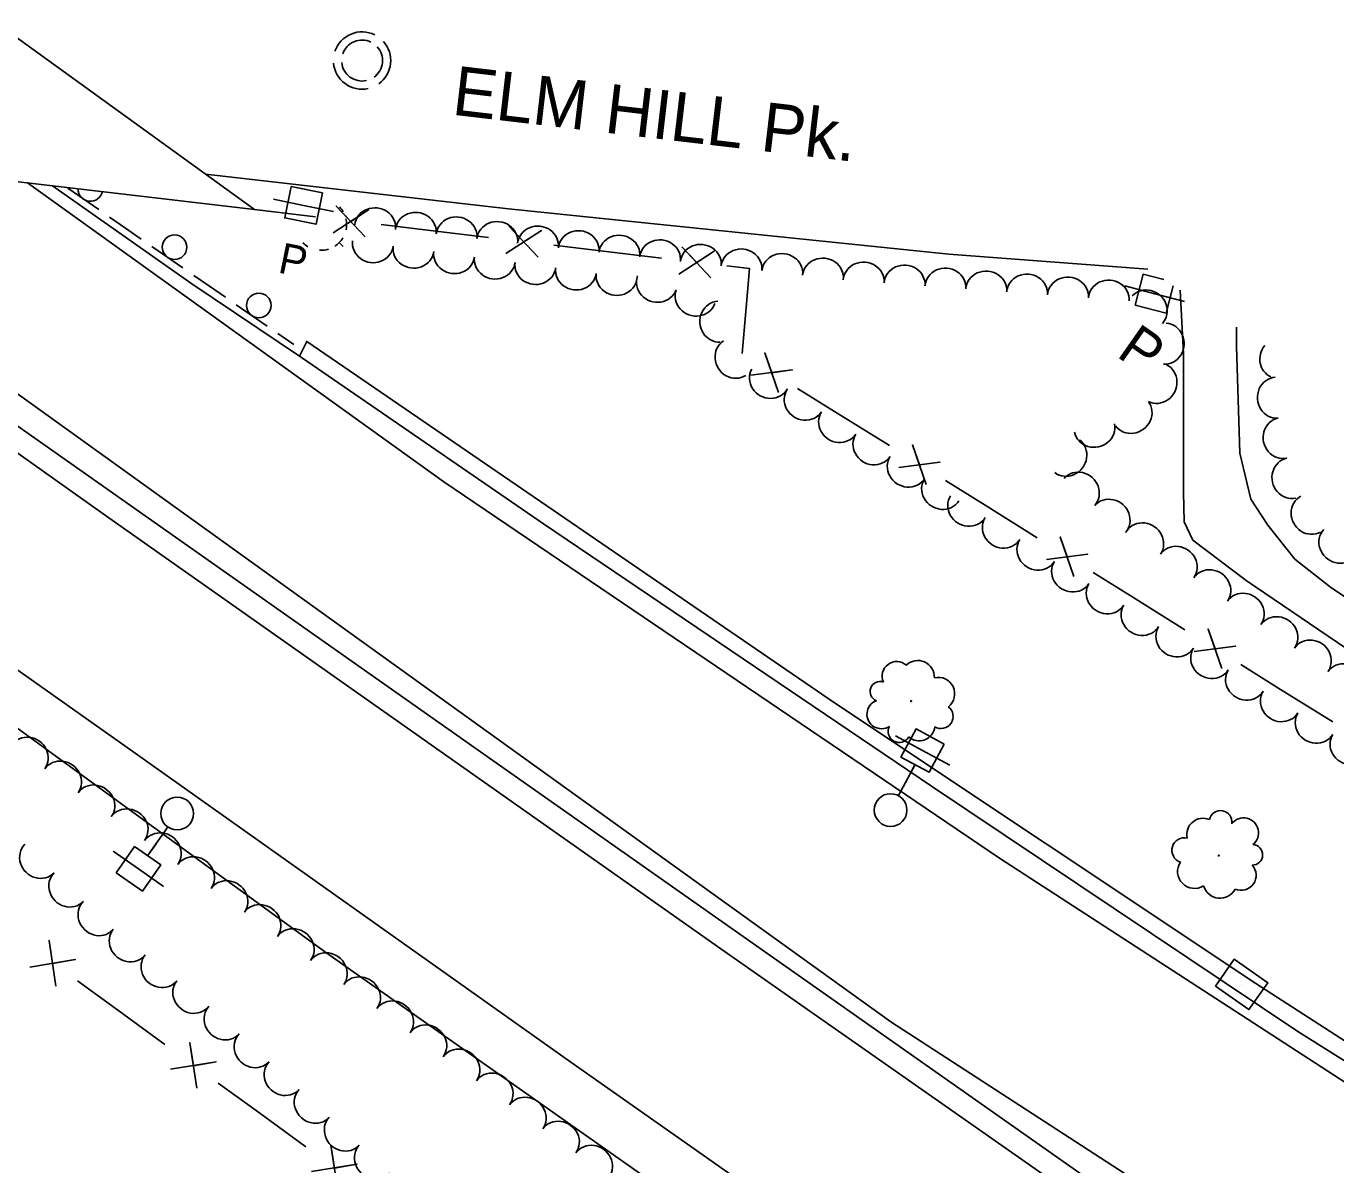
# Model space of a CAD drawing. Extents: x 1746010 to 1754829, y 655801 to 663091.
# Drawn here: x 1750620.5 to 1750940.1, y 659729.4 to 660007.5 of the extents above; entities that cross this region are included whole.
import ezdxf

# ---------------------------------------------------------------- set-up
doc = ezdxf.new("R2010")
doc.units = 0
for name, color, linetype in [('SURVEY - AERIAL SURVEY - Photo Control - Points - Elevations', 7, 'Continuous'), ('SURVEY - AERIAL SURVEY - Photo Control - Points - Locators', 7, 'Continuous'), ('SURVEY - AERIAL SURVEY - Photo Control - Points - Numbers', 7, 'Continuous'), ('SURVEY - CENTERLINE - Existing Roads - Development', 7, 'Continuous'), ('SURVEY - CENTERLINE - Existing Roads Curve Text', 7, 'Continuous'), ('SURVEY - CENTERLINE - Existing Roads Text', 7, 'Continuous'), ('SURVEY - CENTERLINE - Preliminary - Development', 7, 'Continuous'), ('SURVEY - CONTROL - Points - Numbers', 7, 'Continuous')]:
    doc.layers.add(name, color=color, linetype=linetype)

msp = doc.modelspace()

# ---------------------------------------------------------------- linework, layer by layer
at = {"layer": 'SURVEY - AERIAL SURVEY - Photo Control - Points - Elevations'}
for points in [[(1750204.41, 660084.58), (1750567.39, 660041.45), (1750676.22, 659962.69), (1750316.04, 660004.98)], [(1751901.75, 659229.66), (1751903.78, 659232.49), (1751820.15, 659271.12), (1751720.09, 659319), (1751608.79, 659375.48), (1751511.86, 659425.67), (1751414.79, 659477.82), (1751309.42, 659535.79), (1751238.02, 659576.37), (1751119.98, 659647.33), (1751011.07, 659715.27), (1750920.63, 659773.68), (1750818.05, 659842.07), (1750688.97, 659930.51), (1750687.2, 659926.86)]]:
    msp.add_lwpolyline(points, dxfattribs=at)
at = {"layer": 'SURVEY - AERIAL SURVEY - Photo Control - Points - Locators'}
for points in [[(1751850.89, 659069.97), (1751836.71, 659078.71), (1751698.09, 659167.45), (1751556.82, 659259.91), (1751409.51, 659356.6), (1751240.26, 659471.26), (1751108.21, 659560.28), (1750949.44, 659670.61), (1750790.01, 659782.16), (1750639.25, 659888.39), (1750537.27, 659960.87), (1750507.28, 659982.53)], [(1751692.52, 659270.52), (1751605.65, 659313.28), (1751476.09, 659381.66), (1751353.72, 659447.67), (1751225.98, 659520.03), (1751088.26, 659602.44), (1750950.33, 659687.25), (1750831.52, 659764.33), (1750532.19, 659979.6)], [(1750664.23, 659971.37), (1750738.22, 659962.83), (1750845.67, 659951.8), (1750894.23, 659948.17)], [(1751980.95, 659190.5), (1751865.03, 659241.97), (1751755.82, 659292.86), (1751627.46, 659356.04), (1751498.69, 659424), (1751376.94, 659489.68), (1751250.14, 659561.52), (1751113.15, 659643.48), (1750975.97, 659727.83), (1750858.05, 659804.33), (1750722.4, 659896.24), (1750620.83, 659969.19)], [(1750687.69, 659926.53), (1750660.89, 659944.53), (1750626.94, 659968.47)], [(1751811.46, 659040.6), (1751803.54, 659045.66), (1751651.7, 659139.14), (1751560.97, 659192.86), (1751430.95, 659277.83), (1751226.31, 659416.5), (1751044.68, 659538.71), (1750870.37, 659656.91), (1750693.9, 659781.14), (1750567.77, 659872.76), (1750445.81, 659959.59)], [(1750464.75, 659959.09), (1750533.91, 659909.95), (1750645.13, 659831.38), (1750753.4, 659754.5), (1750870.59, 659672.13), (1750959.5, 659609.93), (1751081.2, 659527.03), (1751199.52, 659445.74), (1751320.31, 659364.23), (1751443.12, 659281.31), (1751559.93, 659204.83), (1751660.4, 659140.92), (1751744.29, 659087.1), (1751814.04, 659042.53)], [(1750902.16, 659942.97), (1750902.94, 659927.48), (1750902.95, 659893.71), (1750903.13, 659886.46), (1750905.25, 659881.98), (1750918.24, 659872.14), (1750993.75, 659820.81), (1750998.91, 659830.33), (1750938.84, 659870.48), (1750930.13, 659877.33), (1750923.58, 659885.66), (1750919.37, 659891.98), (1750916.72, 659903.21), (1750915.86, 659929.32), (1750915.87, 659933.99)], [(1751981.66, 659195.26), (1751889.68, 659234.85), (1751784.21, 659284.64), (1751694.2, 659328.1), (1751603.81, 659373.71), (1751512.94, 659420.78), (1751440.06, 659459.77), (1751340.52, 659515.91), (1751224.32, 659581.45), (1751125.19, 659640.31), (1751025.2, 659702.76), (1750930.86, 659762.02), (1750841.47, 659821.93), (1750746.73, 659885.97), (1750687.69, 659926.53)]]:
    msp.add_lwpolyline(points, dxfattribs=at)
at = {"layer": 'SURVEY - AERIAL SURVEY - Photo Control - Points - Numbers'}
for points in [[(1751210.77, 659498.28), (1751086.47, 659583.36), (1750914.66, 659701.33), (1750734.42, 659828.18), (1750551.67, 659956.79), (1750517.76, 659981.3)], [(1750638.18, 659962.67), (1750630.61, 659967.9)], [(1750644.68, 659958.17), (1750640.81, 659960.84)], [(1750648.54, 659955.5), (1750644.68, 659958.17)], [(1750658.74, 659948.44), (1750651.17, 659953.68)], [(1750665.24, 659943.95), (1750661.37, 659946.62)], [(1750669.1, 659941.27), (1750665.24, 659943.95)], [(1750679.3, 659934.22), (1750671.74, 659939.45)], [(1750685.8, 659929.72), (1750681.93, 659932.4)]]:
    msp.add_lwpolyline(points, dxfattribs=at)
for centre, start in [((1750636.14, 659967.72), 179.5986), ((1750656.7, 659953.5), 348.595), ((1750677.26, 659939.28), 348.595)]:
    msp.add_arc(centre, 3, start, 348.581, dxfattribs=at)
at = {"layer": 'SURVEY - CENTERLINE - Existing Roads - Development'}
for points in [[(1750676.22, 659962.69), (1750691.12, 659960.91)], [(1750695.38, 659956.99), (1750704.02, 659962.61), (1750699.75, 659959.8), (1750696.17, 659963.55), (1750703.22, 659956.06)], [(1750707.1, 659959.01), (1750718.43, 659957.66)], [(1750737.58, 659951.96), (1750746.22, 659957.59), (1750741.95, 659954.77), (1750738.38, 659958.52), (1750745.43, 659951.03)], [(1750718.43, 659957.66), (1750733.32, 659955.88)], [(1750749.31, 659953.98), (1750760.63, 659952.63)], [(1750760.63, 659952.63), (1750775.53, 659950.85)], [(1750779.79, 659946.94), (1750788.42, 659952.56), (1750784.16, 659949.74), (1750780.58, 659953.49), (1750787.63, 659946)], [(1750791.51, 659948.95), (1750797.07, 659948.29), (1750796.56, 659942.51)], [(1750796.56, 659942.51), (1750795.25, 659927.58)], [(1750797.38, 659922.22), (1750807.45, 659923.52), (1750802.46, 659922.84), (1750800.74, 659927.7), (1750804.08, 659918.04)], [(1750808.78, 659919), (1750818.45, 659912.97)], [(1750818.45, 659912.97), (1750831.18, 659905.04)], [(1750833.45, 659899.74), (1750843.52, 659901.04), (1750838.53, 659900.37), (1750836.81, 659905.22), (1750840.15, 659895.56)], [(1750844.85, 659896.52), (1750854.52, 659890.49)], [(1750854.52, 659890.49), (1750867.25, 659882.56)], [(1750869.52, 659877.26), (1750879.59, 659878.57), (1750874.59, 659877.89), (1750872.88, 659882.74), (1750876.22, 659873.08)], [(1750880.92, 659874.04), (1750890.59, 659868.01)], [(1750890.59, 659868.01), (1750903.32, 659860.08)], [(1750905.59, 659854.78), (1750915.66, 659856.09), (1750910.67, 659855.41), (1750908.95, 659860.27), (1750912.29, 659850.61)], [(1750916.99, 659851.57), (1750926.66, 659845.54)], [(1750926.66, 659845.54), (1750939.39, 659837.6)], [(1750621.35, 659777.74), (1750632.45, 659779.57), (1750626.94, 659778.63), (1750626.05, 659784.22), (1750627.74, 659773.1)], [(1750632.99, 659774.36), (1750642.21, 659767.66)], [(1750642.21, 659767.66), (1750654.34, 659758.84)], [(1750655.74, 659752.76), (1750666.83, 659754.59), (1750661.32, 659753.65), (1750660.44, 659759.23), (1750662.13, 659748.12)], [(1750667.37, 659749.38), (1750676.59, 659742.68)], [(1750676.59, 659742.68), (1750688.73, 659733.86)], [(1750690.12, 659727.78), (1750701.21, 659729.61), (1750695.71, 659728.66), (1750694.82, 659734.25), (1750696.51, 659723.14)]]:
    msp.add_lwpolyline(points, dxfattribs=at)
at = {"layer": 'SURVEY - CENTERLINE - Existing Roads Curve Text'}
for p, q in [((1750688.18, 659963.7), (1750680.83, 659965.2)), ((1750688.18, 659963.7), (1750695.53, 659962.19)), ((1750697.84, 659953.64), (1750696.85, 659954.63)), ((1750895.94, 659942.14), (1750888.68, 659944.03)), ((1750895.94, 659942.14), (1750903.2, 659940.24)), ((1750839.28, 659830.59), (1750832.67, 659834.15)), ((1750839.28, 659830.59), (1750845.89, 659827.04)), ((1750833.31, 659819.49), (1750837.43, 659827.16)), ((1750837.24, 659826.81), (1750835.73, 659823.99)), ((1750655.1, 659812.03), (1750650.11, 659804.9)), ((1750650.34, 659805.22), (1750652.18, 659807.85)), ((1750647.88, 659801.7), (1750641.73, 659806)), ((1750647.88, 659801.7), (1750654.02, 659797.4))]:
    msp.add_line(p, q, dxfattribs=at)
for points in [[(1750685.14, 659968.3), (1750692.79, 659966.74), (1750691.22, 659959.09), (1750683.58, 659960.66)], [(1750844.56, 659832.18), (1750840.87, 659825.31), (1750834, 659829.01), (1750837.69, 659835.88)], [(1750642.45, 659800.74), (1750646.92, 659807.13), (1750653.31, 659802.66), (1750648.84, 659796.27)]]:
    msp.add_lwpolyline(points, close=True, dxfattribs=at)
msp.add_lwpolyline([(1750900.48, 659944.08), (1750898.73, 659937.38), (1750891.18, 659939.35), (1750893.15, 659946.9), (1750898.18, 659945.58)], dxfattribs=at)
for centre in [(1750657.34, 659815.22), (1750831.47, 659816.06)]:
    msp.add_circle(centre, 4, dxfattribs=at)
for start, end in [(30.0335, 43.9229), (348.4097, 13.1798), (302.3679, 328.8832), (224.847, 239.4679), (266.7248, 287.0674)]:
    msp.add_arc((1750692.44, 659958.99), 6.25, start, end, dxfattribs=at)
at = {"layer": 'SURVEY - CENTERLINE - Existing Roads Text'}
for centre, radius in [((1750836.48, 659842.68), 0.123), ((1750911.57, 659804.96), 0.128)]:
    msp.add_circle(centre, radius, dxfattribs=at)
for centre, radius, start, end in [((1750838.13, 659848.55), 4.03, 356.9893, 134.5135), ((1750832.94, 659848.79), 3.54, 47.9365, 204.7255), ((1750828.89, 659845.03), 2.43, 70.0527, 248.7983), ((1750843.1, 659844.45), 4.01, 307.8851, 103.7236), ((1750829.23, 659839.45), 3.53, 110.0734, 303.4931), ((1750843.79, 659838.92), 2.95, 238.138, 53.1383), ((1750833.56, 659835.27), 2.69, 152.6921, 330.0112), ((1750838.44, 659836.76), 3.81, 227.9791, 354.8248), ((1750912.01, 659813.17), 2.78, 351.1185, 168.4377), ((1750907.72, 659810.13), 3.93, 66.4056, 193.2512), ((1750917.63, 659810.5), 3.65, 308.4999, 141.9195), ((1750903.18, 659806.26), 3.05, 76.5645, 251.5648), ((1750919.77, 659805.14), 2.51, 268.4792, 87.2248), ((1750905.66, 659801.07), 4.14, 146.3116, 302.1501), ((1750917.04, 659800.13), 3.65, 246.363, 43.1519), ((1750911.88, 659798.67), 4.16, 195.4158, 332.94)]:
    msp.add_arc(centre, radius, start, end, dxfattribs=at)
for centre, major_axis, start_param in [((1750705.66, 659958.41), (4.97, -0.56), 0), ((1750715.59, 659957.29), (4.97, -0.56), 0), ((1750725.53, 659956.18), (4.97, -0.56), 0), ((1750735.46, 659955.06), (4.97, -0.56), 0), ((1750745.4, 659953.94), (4.97, -0.56), 0), ((1750705.11, 659954.42), (-4.96, 0.66), 0), ((1750755.34, 659952.83), (4.97, -0.56), 0), ((1750765.27, 659951.71), (4.97, -0.56), 0), ((1750775.21, 659950.59), (4.97, -0.56), 0), ((1750715.02, 659953.09), (-4.96, 0.66), 0), ((1750724.93, 659951.76), (-4.96, 0.66), 0), ((1750785.14, 659949.47), (4.97, -0.56), 0), ((1750795.08, 659948.36), (4.97, -0.56), 0), ((1750805.02, 659947.24), (4.97, -0.56), 0), ((1750734.85, 659950.43), (-4.96, 0.66), 0), ((1750744.76, 659949.1), (-4.96, 0.66), 0), ((1750814.95, 659946.12), (4.97, -0.56), 0), ((1750824.9, 659945.16), (4.99, -0.37), 0), ((1750834.88, 659944.42), (4.99, -0.37), 0), ((1750844.85, 659943.69), (4.99, -0.37), 0), ((1750754.67, 659947.77), (-4.96, 0.66), 0), ((1750764.58, 659946.44), (-4.96, 0.66), 0), ((1750774.41, 659944.78), (-4.71, 1.69), 0), ((1750854.82, 659942.96), (4.99, -0.37), 0), ((1750864.79, 659942.23), (4.99, -0.37), 0), ((1750874.77, 659941.49), (4.99, -0.37), 0), ((1750884.74, 659940.76), (4.99, -0.37), 0), ((1750783.83, 659941.41), (-4.71, 1.69), 0), ((1750894.12, 659938.22), (3.69, -3.37), 0), ((1750789.61, 659935.32), (-0.29, 4.99), 0), ((1750898.41, 659929.95), (-0.35, -4.99), 0), ((1750793.4, 659926.4), (-2.71, 4.2), 0), ((1750926.36, 659926.39), (2.11, 4.53), 1.313708), ((1750801.94, 659921.34), (-4.38, 2.41), 0), ((1750896.61, 659920.3), (-2.21, -4.49), 0), ((1750925.7, 659916.74), (-0.34, 4.99), 0), ((1750810.41, 659916.03), (-4.19, 2.72), 0), ((1750818.8, 659910.59), (-4.19, 2.72), 0), ((1750890.39, 659912.84), (-4.02, -2.98), 0), ((1750881.26, 659909.35), (-4.9, -1), 0), ((1750927.11, 659906.89), (-1.08, 4.88), 0), ((1750827.18, 659905.14), (-4.19, 2.72), 0), ((1750874.56, 659902.44), (-3.01, -3.99), 0), ((1750835.57, 659899.7), (-4.19, 2.72), 0), ((1750929.27, 659897.13), (-1.08, 4.88), 0), ((1750877.55, 659893.75), (3.75, -3.31), 0), ((1750843.96, 659894.26), (-4.19, 2.72), 0), ((1750850.34, 659890.15), (-4.22, 2.68), 0), ((1750885.05, 659887.12), (3.75, -3.31), 0), ((1750934.01, 659888.33), (-2.38, 4.4), 0), ((1750858.78, 659884.8), (-4.22, 2.68), 0), ((1750893.22, 659881.39), (4.1, -2.87), 0), ((1750940.89, 659881.17), (-3.67, 3.4), 0), ((1750867.23, 659879.44), (-4.22, 2.68), 0), ((1750901.41, 659875.66), (4.1, -2.87), 0), ((1750875.67, 659874.09), (-4.22, 2.68), 0), ((1750909.59, 659869.94), (4.1, -2.87), 0), ((1750884.13, 659868.75), (-4.25, 2.63), 0), ((1750917.77, 659864.21), (4.1, -2.87), 0), ((1750892.63, 659863.49), (-4.25, 2.63), 0), ((1750925.96, 659858.48), (4.1, -2.87), 0), ((1750901.13, 659858.22), (-4.25, 2.63), 0), ((1750934.14, 659852.76), (4.1, -2.87), 0), ((1750909.63, 659852.95), (-4.25, 2.63), 0), ((1750918.13, 659847.69), (-4.25, 2.63), 0), ((1750942.28, 659846.97), (4.05, -2.94), 0), ((1750926.64, 659842.42), (-4.25, 2.63), 0), ((1750935.14, 659837.16), (-4.25, 2.63), 0), ((1750620.97, 659829.06), (4.06, -2.92), 0), ((1750943.64, 659831.89), (-4.25, 2.63), 0), ((1750629.08, 659823.22), (4.06, -2.92), 0), ((1750637.2, 659817.38), (4.06, -2.92), 0), ((1750645.32, 659811.54), (4.06, -2.92), 0), ((1750653.43, 659805.7), (4.06, -2.92), 0), ((1750623.73, 659804.22), (-3.57, 3.5), 0), ((1750661.55, 659799.86), (4.06, -2.92), 0), ((1750630.86, 659797.23), (-3.57, 3.5), 0), ((1750669.67, 659794.02), (4.06, -2.92), 0), ((1750637.99, 659790.24), (-3.57, 3.5), 0), ((1750677.77, 659788.16), (4.05, -2.94), 0), ((1750645.63, 659783.82), (-3.88, 3.15), 0), ((1750685.86, 659782.28), (4.05, -2.94), 0), ((1750653.39, 659777.53), (-3.88, 3.15), 0), ((1750693.95, 659776.4), (4.05, -2.94), 0), ((1750702.04, 659770.53), (4.05, -2.94), 0), ((1750661.15, 659771.24), (-3.88, 3.15), 0), ((1750710.14, 659764.65), (4.05, -2.94), 0), ((1750668.77, 659764.79), (-3.67, 3.4), 0), ((1750718.23, 659758.78), (4.05, -2.94), 0), ((1750676.1, 659758), (-3.67, 3.4), 0), ((1750726.32, 659752.9), (4.05, -2.94), 0), ((1750683.44, 659751.21), (-3.67, 3.4), 0), ((1750734.41, 659747.03), (4.05, -2.94), 0), ((1750690.78, 659744.43), (-3.67, 3.4), 0), ((1750742.5, 659741.15), (4.05, -2.94), 0), ((1750698.11, 659737.64), (-3.67, 3.4), 0), ((1750750.6, 659735.27), (4.05, -2.94), 0), ((1750758.69, 659729.4), (4.05, -2.94), 0), ((1750705.45, 659730.86), (-3.67, 3.4), 0)]:
    msp.add_ellipse(centre, major_axis=major_axis, ratio=0.940188, start_param=start_param, end_param=3.141593, dxfattribs=at)
at = {"layer": 'SURVEY - CENTERLINE - Preliminary - Development'}
msp.add_line((1750917.13, 659773.5), (1750917.13, 659773.5), dxfattribs=at)
msp.add_lwpolyline([(1750910.74, 659773.09), (1750915.33, 659779.64), (1750923.52, 659773.91), (1750918.94, 659767.35), (1750910.74, 659773.09)], dxfattribs=at)
for radius, start, end in [(7, 63.9805, 161.2752), (5, 64.7829, 161.2211), (7, 305.5742, 42.0205), (5, 305.5715, 42.1165), (7, 185.4172, 282.2103), (5, 185.3352, 282.1698)]:
    msp.add_arc((1750702.47, 659999.08), radius, start, end, dxfattribs=at)

# ---------------------------------------------------------------- texts
at = {"layer": 'SURVEY - CENTERLINE - Existing Roads Curve Text'}
for height, rotation, p in [(7.48, 348.4508, (1750681.68, 659947.36)), (10, 325.02, (1750886.33, 659926.99))]:
    msp.add_text('P', height=height, rotation=rotation, dxfattribs=at).set_placement(p)
at = {"layer": 'SURVEY - CONTROL - Points - Numbers'}
msp.add_text('ELM HILL Pk.', height=12, rotation=353.3019, dxfattribs=at).set_placement((1750724.16, 659985.9))

doc.saveas('drawing.dxf')
